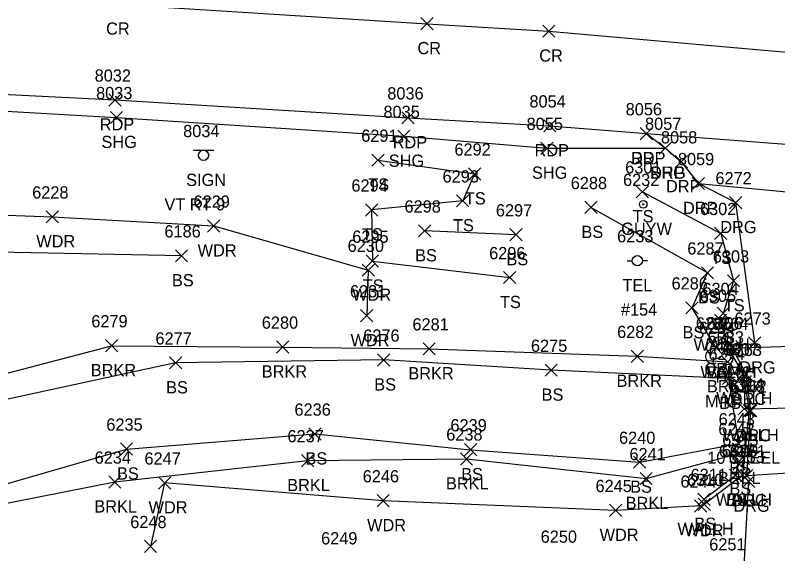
# Model space of a CAD drawing. Extents: x 1588028 to 1589597, y 137576 to 138176.
# Drawn here: x 1588574.1 to 1588699, y 137809.3 to 137897.5 of the extents above; entities that cross this region are included whole.
import ezdxf

# ---------------------------------------------------------------- set-up
doc = ezdxf.new("R2010")
doc.units = 0
for name, color, linetype in [('D_A', 7, 'Continuous'), ('D_C', 7, 'Continuous'), ('D_I', 7, 'Continuous'), ('D_TIC', 7, 'Continuous'), ('DCP', 7, 'Continuous'), ('DHW', 7, 'Continuous'), ('L_A', 7, 'Continuous'), ('L_C', 7, 'Continuous'), ('L_I', 7, 'Continuous'), ('L_TIC', 7, 'Continuous'), ('LAWA', 7, 'Continuous'), ('LAWE', 7, 'Continuous'), ('LELB', 7, 'Continuous'), ('LTD', 7, 'Continuous'), ('P_A', 7, 'Continuous'), ('P_I', 7, 'Continuous'), ('P_TIC', 7, 'Continuous'), ('PET', 7, 'Continuous'), ('PRC', 7, 'Continuous'), ('PSU', 7, 'Continuous'), ('R_A', 7, 'Continuous'), ('R_I', 7, 'Continuous'), ('R_TIC', 7, 'Continuous'), ('RDG', 7, 'Continuous'), ('RDP', 7, 'Continuous'), ('S_A', 7, 'Continuous'), ('S_C', 7, 'Continuous'), ('S_I', 7, 'Continuous'), ('SSGN', 7, 'Continuous'), ('U_A', 7, 'Continuous'), ('U_C', 7, 'Continuous'), ('U_I', 7, 'Continuous'), ('UP', 7, 'Continuous'), ('UPGW', 7, 'Continuous')]:
    doc.layers.add(name, color=color, linetype=linetype)

msp = doc.modelspace()

# ---------------------------------------------------------------- linework, layer by layer
at = {"layer": 'D_TIC'}
for points in [[(1588688.65, 137846.55), (1588690.65, 137848.55)], [(1588690.65, 137846.55), (1588688.65, 137848.55)], [(1588689.78, 137842.06), (1588691.78, 137844.06)], [(1588691.78, 137842.06), (1588689.78, 137844.06)], [(1588692.37, 137837.77), (1588694.37, 137839.77)], [(1588694.37, 137837.77), (1588692.37, 137839.77)], [(1588692.57, 137832.03), (1588694.57, 137834.03)], [(1588694.57, 137832.03), (1588692.57, 137834.03)], [(1588693.38, 137831.74), (1588695.38, 137833.74)], [(1588695.38, 137831.74), (1588693.38, 137833.74)], [(1588692.29, 137821.18), (1588694.29, 137823.18)], [(1588694.29, 137821.18), (1588692.29, 137823.18)], [(1588686, 137816.39), (1588688, 137818.39)], [(1588688, 137816.39), (1588686, 137818.39)]]:
    msp.add_lwpolyline(points, dxfattribs=at)
at = {"layer": 'DCP'}
msp.add_lwpolyline([(1588693.57, 137833.03), (1588709.71, 137833.36)], dxfattribs=at)
at = {"layer": 'DHW'}
msp.add_lwpolyline([(1588689.65, 137847.55), (1588690.78, 137843.06), (1588693.37, 137838.77), (1588694.38, 137832.74), (1588693.29, 137822.18), (1588687, 137817.39)], dxfattribs=at)
at = {"layer": 'L_TIC'}
for points in [[(1588632.53, 137872.75), (1588634.53, 137874.75)], [(1588634.53, 137872.75), (1588632.53, 137874.75)], [(1588648.36, 137870.5), (1588650.36, 137872.5)], [(1588650.36, 137870.5), (1588648.36, 137872.5)], [(1588675.86, 137867.57), (1588677.86, 137869.57)], [(1588677.86, 137867.57), (1588675.86, 137869.57)], [(1588646.42, 137866.09), (1588648.42, 137868.09)], [(1588648.42, 137866.09), (1588646.42, 137868.09)], [(1588667.43, 137865.01), (1588669.43, 137867.01)], [(1588669.43, 137865.01), (1588667.43, 137867.01)], [(1588631.49, 137864.6), (1588633.49, 137866.6)], [(1588633.49, 137864.6), (1588631.49, 137866.6)], [(1588579.18, 137863.47), (1588581.18, 137865.47)], [(1588581.18, 137863.47), (1588579.18, 137865.47)], [(1588605.62, 137861.97), (1588607.62, 137863.97)], [(1588607.62, 137861.97), (1588605.62, 137863.97)], [(1588640.18, 137861.17), (1588642.18, 137863.17)], [(1588642.18, 137861.17), (1588640.18, 137863.17)], [(1588655.15, 137860.54), (1588657.15, 137862.54)], [(1588657.15, 137860.54), (1588655.15, 137862.54)], [(1588688.69, 137860.76), (1588690.69, 137862.76)], [(1588690.69, 137860.76), (1588688.69, 137862.76)], [(1588600.33, 137857.09), (1588602.33, 137859.09)], [(1588602.33, 137857.09), (1588600.33, 137859.09)], [(1588631.62, 137856.22), (1588633.62, 137858.22)], [(1588633.62, 137856.22), (1588631.62, 137858.22)], [(1588630.95, 137854.73), (1588632.95, 137856.73)], [(1588632.95, 137854.73), (1588630.95, 137856.73)], [(1588686.52, 137854.29), (1588688.52, 137856.29)], [(1588688.52, 137854.29), (1588686.52, 137856.29)], [(1588654.12, 137853.53), (1588656.12, 137855.53)], [(1588656.12, 137853.53), (1588654.12, 137855.53)], [(1588690.79, 137852.99), (1588692.79, 137854.99)], [(1588692.79, 137852.99), (1588690.79, 137854.99)], [(1588684, 137848.57), (1588686, 137850.57)], [(1588686, 137848.57), (1588684, 137850.57)], [(1588689.09, 137847.66), (1588691.09, 137849.66)], [(1588691.09, 137847.66), (1588689.09, 137849.66)], [(1588630.68, 137847.28), (1588632.68, 137849.28)], [(1588632.68, 137847.28), (1588630.68, 137849.28)], [(1588588.88, 137842.37), (1588590.88, 137844.37)], [(1588590.88, 137842.37), (1588588.88, 137844.37)], [(1588616.9, 137842.15), (1588618.9, 137844.15)], [(1588618.9, 137842.15), (1588616.9, 137844.15)], [(1588640.92, 137841.86), (1588642.92, 137843.86)], [(1588642.92, 137841.86), (1588640.92, 137843.86)], [(1588687.93, 137842.01), (1588689.93, 137844.01)], [(1588689.93, 137842.01), (1588687.93, 137844.01)], [(1588633.48, 137840.03), (1588635.48, 137842.03)], [(1588635.48, 137840.03), (1588633.48, 137842.03)], [(1588675.03, 137840.63), (1588677.03, 137842.63)], [(1588677.03, 137840.63), (1588675.03, 137842.63)], [(1588599.38, 137839.56), (1588601.38, 137841.56)], [(1588601.38, 137839.56), (1588599.38, 137841.56)], [(1588689.85, 137839.73), (1588691.85, 137841.73)], [(1588691.85, 137839.73), (1588689.85, 137841.73)], [(1588660.91, 137838.36), (1588662.91, 137840.36)], [(1588662.91, 137838.36), (1588660.91, 137840.36)], [(1588690, 137837.01), (1588692, 137839.01)], [(1588692, 137837.01), (1588690, 137839.01)], [(1588622.21, 137827.91), (1588624.21, 137829.91)], [(1588624.21, 137827.91), (1588622.21, 137829.91)], [(1588691.66, 137826.33), (1588693.66, 137828.33)], [(1588693.66, 137826.33), (1588691.66, 137828.33)], [(1588591.33, 137825.45), (1588593.33, 137827.45)], [(1588593.33, 137825.45), (1588591.33, 137827.45)], [(1588647.72, 137825.34), (1588649.72, 137827.34)], [(1588649.72, 137825.34), (1588647.72, 137827.34)], [(1588647.03, 137823.83), (1588649.03, 137825.83)], [(1588649.03, 137823.83), (1588647.03, 137825.83)], [(1588691.6, 137824.72), (1588693.6, 137826.72)], [(1588693.6, 137824.72), (1588691.6, 137826.72)], [(1588621.01, 137823.55), (1588623.01, 137825.55)], [(1588623.01, 137823.55), (1588621.01, 137825.55)], [(1588675.42, 137823.29), (1588677.42, 137825.29)], [(1588677.42, 137823.29), (1588675.42, 137825.29)], [(1588691.68, 137822.96), (1588693.68, 137824.96)], [(1588693.68, 137822.96), (1588691.68, 137824.96)], [(1588589.41, 137820.05), (1588591.41, 137822.05)], [(1588591.41, 137820.05), (1588589.41, 137822.05)], [(1588676.48, 137820.62), (1588678.48, 137822.62)], [(1588678.48, 137820.62), (1588676.48, 137822.62)], [(1588691.13, 137821.14), (1588693.13, 137823.14)], [(1588693.13, 137821.14), (1588691.13, 137823.14)], [(1588597.57, 137819.9), (1588599.57, 137821.9)], [(1588599.57, 137819.9), (1588597.57, 137821.9)], [(1588633.39, 137816.99), (1588635.39, 137818.99)], [(1588635.39, 137816.99), (1588633.39, 137818.99)], [(1588685.94, 137817.21), (1588687.94, 137819.21)], [(1588687.94, 137817.21), (1588685.94, 137819.21)], [(1588671.48, 137815.4), (1588673.48, 137817.4)], [(1588673.48, 137815.4), (1588671.48, 137817.4)], [(1588685.41, 137816.13), (1588687.41, 137818.13)], [(1588687.41, 137816.13), (1588685.41, 137818.13)], [(1588595.25, 137809.5), (1588597.25, 137811.5)], [(1588597.25, 137809.5), (1588595.25, 137811.5)]]:
    msp.add_lwpolyline(points, dxfattribs=at)
at = {"layer": 'LAWA'}
for points in [[(1588398.21, 137876.79), (1588441.82, 137872.12), (1588481.62, 137869.65), (1588505.62, 137869.07), (1588523.45, 137867.77), (1588551.7, 137865.51), (1588580.18, 137864.47), (1588606.62, 137862.97), (1588631.95, 137855.73), (1588631.68, 137848.28)], [(1588686.41, 137817.13), (1588672.48, 137816.4), (1588634.39, 137817.99), (1588598.57, 137820.9), (1588596.25, 137810.5)]]:
    msp.add_lwpolyline(points, dxfattribs=at)
at = {"layer": 'LAWE'}
for points in [[(1588351.94, 137757.61), (1588394.8, 137793.11), (1588433.62, 137803.03), (1588480.63, 137811.17), (1588520.35, 137821.08), (1588567.54, 137837.49), (1588589.88, 137843.37), (1588617.9, 137843.15), (1588641.92, 137842.86), (1588676.03, 137841.63), (1588690.85, 137840.73)], [(1588391.31, 137757.57), (1588423.17, 137774.38), (1588459.5, 137784.96), (1588499.39, 137790.91), (1588529.2, 137803.77), (1588565.73, 137816.22), (1588590.41, 137821.05), (1588622.01, 137824.55), (1588648.03, 137824.83), (1588677.48, 137821.62), (1588692.6, 137825.72)]]:
    msp.add_lwpolyline(points, dxfattribs=at)
at = {"layer": 'LELB'}
for points in [[(1588633.53, 137873.75), (1588649.36, 137871.5), (1588647.42, 137867.09), (1588632.49, 137865.6), (1588632.62, 137857.22), (1588655.12, 137854.53)], [(1588676.86, 137868.57), (1588689.69, 137861.76), (1588691.79, 137853.99), (1588690.09, 137848.66)], [(1588688.93, 137843.01), (1588685, 137849.57), (1588687.52, 137855.29), (1588668.43, 137866.01)], [(1588656.15, 137861.54), (1588641.18, 137862.17)], [(1588601.33, 137858.09), (1588565.74, 137858.78), (1588552.32, 137849.2), (1588523.84, 137845.09), (1588499.09, 137858.03), (1588496.21, 137836.26), (1588469.92, 137835.97)], [(1588391.4, 137759.65), (1588422.67, 137775.93), (1588458.34, 137787.99), (1588495.41, 137796.88), (1588527.54, 137805.18), (1588563.3, 137818.09), (1588592.33, 137826.45), (1588623.21, 137828.91), (1588648.72, 137826.34), (1588676.42, 137824.29), (1588692.66, 137827.33), (1588691, 137838.01), (1588661.91, 137839.36), (1588634.48, 137841.03), (1588600.38, 137840.56), (1588568.3, 137833.61)], [(1588686.94, 137818.21), (1588692.13, 137822.14), (1588692.68, 137823.96)]]:
    msp.add_lwpolyline(points, dxfattribs=at)
at = {"layer": 'LTD'}
msp.add_line((1588689.43, 137842.3), (1588689.43, 137842.3), dxfattribs=at)
msp.add_line((1588689.43, 137842.3), (1588689.43, 137842.3), dxfattribs=at)
msp.add_arc((1588689.48, 137843.74), 1.05, 335.5272, 180.9563, dxfattribs=at)
for centre, major_axis, ratio, start_param, end_param in [((1588688.64, 137842.97), (1.21, -0.51), 0.895232, 1.570796, 4.712389), ((1588689.22, 137842.76), (-0.208, -0.792), 0.645439, 3.141593, 6.283185), ((1588690.47, 137842.89), (-1.14, -0.48), 0.949671, 1.570796, 4.712389), ((1588688.35, 137841.59), (0.58, -1.04), 0.959034, 3.141593, 6.283185), ((1588689.93, 137842.14), (-0.5, 0.667), 0.989748, 3.141593, 6.283185), ((1588690.43, 137841.47), (-1.09, 0.79), 0.841452, 1.570796, 4.712389), ((1588689.43, 137840.8), (0.26, 1.06), 0.942809, 1.570796, 4.712389), ((1588688.97, 137841.55), (-0.625, -0.083), 0.423636, 0, 3.141593)]:
    msp.add_ellipse(centre, major_axis=major_axis, ratio=ratio, start_param=start_param, end_param=end_param, dxfattribs=at)
at = {"layer": 'P_TIC'}
for points in [[(1588640.57, 137895.1), (1588642.57, 137897.1)], [(1588642.57, 137895.1), (1588640.57, 137897.1)], [(1588660.53, 137893.88), (1588662.53, 137895.88)], [(1588662.53, 137893.88), (1588660.53, 137895.88)], [(1588589.45, 137882.61), (1588591.45, 137884.61)], [(1588591.45, 137882.61), (1588589.45, 137884.61)], [(1588589.68, 137879.74), (1588591.68, 137881.74)], [(1588591.68, 137879.74), (1588589.68, 137881.74)], [(1588637.45, 137879.69), (1588639.45, 137881.69)], [(1588639.45, 137879.69), (1588637.45, 137881.69)], [(1588660.69, 137878.38), (1588662.69, 137880.38)], [(1588662.69, 137878.38), (1588660.69, 137880.38)], [(1588636.76, 137876.66), (1588638.76, 137878.66)], [(1588638.76, 137876.66), (1588636.76, 137878.66)], [(1588676.51, 137877.09), (1588678.51, 137879.09)], [(1588678.51, 137877.09), (1588676.51, 137879.09)], [(1588660.23, 137874.7), (1588662.23, 137876.7)], [(1588662.23, 137874.7), (1588660.23, 137876.7)], [(1588679.63, 137874.71), (1588681.63, 137876.71)], [(1588681.63, 137874.71), (1588679.63, 137876.71)]]:
    msp.add_lwpolyline(points, dxfattribs=at)
at = {"layer": 'PET'}
msp.add_lwpolyline([(1588419.97, 137892.51), (1588466.09, 137889.91), (1588506.76, 137888.01), (1588548, 137885.78), (1588590.45, 137883.61), (1588638.45, 137880.69), (1588661.69, 137879.38), (1588677.51, 137878.09), (1588721.13, 137874.78), (1588740.19, 137872.99), (1588782.63, 137867.93), (1588820.21, 137862.87), (1588860.26, 137857.26), (1588914.01, 137849.9), (1588927.99, 137847.51)], dxfattribs=at)
at = {"layer": 'PRC'}
msp.add_lwpolyline([(1588420.99, 137907.2), (1588467.18, 137904.92), (1588507.29, 137903.21), (1588549.37, 137901.19), (1588590.55, 137899.3), (1588641.57, 137896.1), (1588661.53, 137894.88), (1588702.39, 137891.26), (1588744.44, 137887.15), (1588784.4, 137882.3), (1588823.71, 137877.3), (1588862.06, 137871.74), (1588917.24, 137863.85)], dxfattribs=at)
at = {"layer": 'PSU'}
msp.add_lwpolyline([(1588419.69, 137889.11), (1588465.62, 137886.91), (1588506.57, 137885.14), (1588547.79, 137883.19), (1588590.68, 137880.74), (1588637.76, 137877.66), (1588661.23, 137875.7), (1588680.63, 137875.71)], dxfattribs=at)
at = {"layer": 'R_TIC'}
for points in [[(1588676.51, 137877.09), (1588678.51, 137879.09)], [(1588678.51, 137877.09), (1588676.51, 137879.09)], [(1588679.63, 137874.71), (1588681.63, 137876.71)], [(1588681.63, 137874.71), (1588679.63, 137876.71)], [(1588682.24, 137872.49), (1588684.24, 137874.49)], [(1588684.24, 137872.49), (1588682.24, 137874.49)], [(1588685.03, 137868.93), (1588687.03, 137870.93)], [(1588687.03, 137868.93), (1588685.03, 137870.93)], [(1588691.14, 137865.8), (1588693.14, 137867.8)], [(1588693.14, 137865.8), (1588691.14, 137867.8)], [(1588694.25, 137842.82), (1588696.25, 137844.82)], [(1588696.25, 137842.82), (1588694.25, 137844.82)], [(1588690.61, 137841.95), (1588692.61, 137843.95)], [(1588692.61, 137841.95), (1588690.61, 137843.95)], [(1588692.86, 137837.68), (1588694.86, 137839.68)], [(1588694.86, 137837.68), (1588692.86, 137839.68)], [(1588693.64, 137831.7), (1588695.64, 137833.7)], [(1588695.64, 137831.7), (1588693.64, 137833.7)], [(1588692.95, 137821.08), (1588694.95, 137823.08)], [(1588694.95, 137821.08), (1588692.95, 137823.08)], [(1588693.29, 137820.17), (1588695.29, 137822.17)], [(1588695.29, 137820.17), (1588693.29, 137822.17)]]:
    msp.add_lwpolyline(points, dxfattribs=at)
at = {"layer": 'RDG'}
for points in [[(1588692.14, 137866.8), (1588686.03, 137869.93)], [(1588692.14, 137866.8), (1588695.25, 137843.82)], [(1588693.3, 137803.33), (1588694.29, 137821.17)]]:
    msp.add_lwpolyline(points, dxfattribs=at)
at = {"layer": 'RDP'}
for points in [[(1588677.51, 137878.09), (1588680.63, 137875.71), (1588683.24, 137873.49), (1588686.03, 137869.93), (1588712.1, 137867.48), (1588714.28, 137870.34), (1588718.55, 137872.99), (1588721.13, 137874.78)], [(1588693.95, 137822.08), (1588694.64, 137832.7), (1588693.86, 137838.68), (1588691.61, 137842.95), (1588709.04, 137843.58), (1588708.54, 137832.84), (1588710.89, 137823.14)], [(1588710.89, 137823.14), (1588693.95, 137822.08)]]:
    msp.add_lwpolyline(points, dxfattribs=at)
at = {"layer": 'SSGN'}
for p, q in [((1588603.32, 137875.38), (1588606.65, 137875.38)), ((1588604.96, 137874.54), (1588604.96, 137874.54))]:
    msp.add_line(p, q, dxfattribs=at)
msp.add_circle((1588604.96, 137874.54), 0.833, dxfattribs=at)
at = {"layer": 'UP'}
for p, q in [((1588674.37, 137857.29), (1588675.2, 137857.29)), ((1588676.03, 137857.29), (1588676.03, 137857.29)), ((1588677.7, 137857.29), (1588676.86, 137857.29)), ((1588676.86, 137857.29), (1588676.86, 137857.29)), ((1588677.7, 137857.29), (1588677.7, 137857.29))]:
    msp.add_line(p, q, dxfattribs=at)
msp.add_circle((1588676.03, 137857.29), 0.833, dxfattribs=at)
at = {"layer": 'UPGW'}
for radius in [0.625, 0.0833]:
    msp.add_circle((1588676.99, 137866.52), radius, dxfattribs=at)

# ---------------------------------------------------------------- texts
at = {"layer": 'D_A'}
for s, p in [('WALLH', (1588685.24, 137842.55)), ('WALLH', (1588686.37, 137838.06)), ('WALLH', (1588688.96, 137833.77)), ('WALLH', (1588689.98, 137827.74)), ('P', (1588692.94, 137828.03)), ('WALLH', (1588688.88, 137817.18)), ('WALLH', (1588682.6, 137812.39))]:
    msp.add_text(s, height=2, dxfattribs=at).set_placement(p)
at = {"layer": 'D_C'}
for s, p in [('CRM', (1588687.02, 137838.55)), ("10'STEEL", (1588687.49, 137824.03))]:
    msp.add_text(s, height=2, dxfattribs=at).set_placement(p)
at = {"layer": 'D_I'}
for s, p in [('6305', (1588686.26, 137850.55)), ('6306', (1588687.34, 137846.06)), ('6307', (1588689.99, 137841.77)), ('6314', (1588690.83, 137836.03)), ('6308', (1588691, 137835.74)), ('6309', (1588689.9, 137825.18)), ('6310', (1588684.18, 137820.39))]:
    msp.add_text(s, height=2, dxfattribs=at).set_placement(p)
at = {"layer": 'L_A'}
for s, p in [('TS', (1588631.94, 137868.75)), ('TS', (1588647.77, 137866.5)), ('TS', (1588675.27, 137863.57)), ('TS', (1588645.83, 137862.09)), ('TS', (1588630.9, 137860.6)), ('BS', (1588666.87, 137861.01)), ('WDR', (1588577.54, 137859.47)), ('WDR', (1588603.98, 137857.97)), ('BS', (1588639.62, 137857.17)), ('BS', (1588654.59, 137856.54)), ('TS', (1588688.1, 137856.76)), ('BS', (1588599.77, 137853.09)), ('TS', (1588631.03, 137852.22)), ('WDR', (1588629.31, 137850.73)), ('BS', (1588685.97, 137850.29)), ('TS', (1588653.52, 137849.53)), ('TS', (1588690.2, 137848.99)), ('BS', (1588683.44, 137844.57)), ('WDR', (1588629.04, 137843.28)), ('TS', (1588688.5, 137843.66)), ('BRKR', (1588586.47, 137838.37)), ('BRKR', (1588614.49, 137838.15)), ('BRKR', (1588638.51, 137837.86)), ('BS', (1588687.37, 137838.01)), ('BRKR', (1588672.62, 137836.63)), ('H', (1588688.86, 137837.3)), ('BS', (1588598.82, 137835.56)), ('BS', (1588632.92, 137836.03)), ('BRKR', (1588687.44, 137835.73)), ('BS', (1588660.35, 137834.36)), ('BS', (1588689.44, 137833.01)), ('BS', (1588621.65, 137823.91)), ('BS', (1588590.77, 137821.45)), ('BS', (1588647.17, 137821.34)), ('BS', (1588691.1, 137822.33)), ('BRKL', (1588689.25, 137820.72)), ('BRKL', (1588618.66, 137819.55)), ('BRKL', (1588644.67, 137819.83)), ('BS', (1588674.86, 137819.29)), ('BS', (1588691.13, 137818.96)), ('BRKL', (1588674.12, 137816.62)), ('BS', (1588690.57, 137817.14)), ('BRKL', (1588587.06, 137816.05)), ('WDR', (1588595.94, 137815.9)), ('WDR', (1588631.75, 137812.99)), ('BS', (1588685.38, 137813.21)), ('WDR', (1588669.85, 137811.4)), ('WDR', (1588683.77, 137812.13))]:
    msp.add_text(s, height=2, dxfattribs=at).set_placement(p)
at = {"layer": 'L_C'}
msp.add_text('M.M', height=2, dxfattribs=at).set_placement((1588687.13, 137833.3))
at = {"layer": 'L_I'}
for s, p in [('6291', (1588630.79, 137876.75)), ('6292', (1588646.06, 137874.5)), ('6301', (1588674.04, 137871.57)), ('6293', (1588644.11, 137870.09)), ('6288', (1588665.12, 137869.01)), ('6228', (1588576.87, 137867.47)), ('6294', (1588629.18, 137868.6)), ('6229', (1588603.31, 137865.97)), ('6298', (1588637.88, 137865.17)), ('6297', (1588652.85, 137864.54)), ('6302', (1588686.3, 137864.76)), ('6186', (1588598.54, 137861.09)), ('6295', (1588629.32, 137860.22)), ('6230', (1588628.56, 137858.73)), ('6296', (1588651.75, 137857.53)), ('6287', (1588684.22, 137858.29)), ('6303', (1588688.4, 137856.99)), ('6286', (1588681.64, 137852.57)), ('6231', (1588628.94, 137851.28)), ('6304', (1588686.7, 137851.66)), ('6279', (1588586.56, 137846.37)), ('6280', (1588614.5, 137846.15)), ('6281', (1588639.18, 137845.86)), ('6285', (1588685.62, 137846.01)), ('6284', (1588686.12, 137845.3)), ('6276', (1588631.12, 137844.03)), ('6282', (1588672.72, 137844.63)), ('6283', (1588687.55, 137843.73)), ('6277', (1588597.07, 137843.56)), ('6275', (1588658.6, 137842.36)), ('6274', (1588687.69, 137841.01)), ('6236', (1588619.85, 137831.91)), ('6243', (1588689.35, 137830.33)), ('6235', (1588589.02, 137829.45)), ('6239', (1588645.41, 137829.34)), ('6242', (1588689.3, 137828.72)), ('6237', (1588618.7, 137827.55)), ('6238', (1588644.72, 137827.83)), ('6240', (1588673.03, 137827.29)), ('6313', (1588689.94, 137826.96)), ('6312', (1588689.39, 137825.14)), ('6234', (1588587.1, 137824.05)), ('6247', (1588595.27, 137823.9)), ('6241', (1588674.74, 137824.62)), ('6311', (1588684.76, 137821.21)), ('6246', (1588631.03, 137820.99)), ('6244', (1588683.1, 137820.13)), ('6245', (1588669.18, 137819.4)), ('6248', (1588592.94, 137813.5)), ('6249', (1588624.21, 137810.83)), ('6250', (1588660.19, 137811.1)), ('6251', (1588687.81, 137809.84))]:
    msp.add_text(s, height=2, dxfattribs=at).set_placement(p)
at = {"layer": 'P_A'}
for s, p in [('CR', (1588588.98, 137894.3)), ('CR', (1588640, 137891.1)), ('CR', (1588659.96, 137889.88)), ('RDP', (1588587.94, 137878.61)), ('SHG', (1588588.22, 137875.74)), ('RDP', (1588635.94, 137875.69)), ('RDP', (1588659.18, 137874.38)), ('SHG', (1588635.3, 137872.66)), ('RDP', (1588675, 137873.09)), ('SHG', (1588658.77, 137870.7)), ('SHG', (1588678.17, 137870.71))]:
    msp.add_text(s, height=2, dxfattribs=at).set_placement(p)
at = {"layer": 'P_I'}
for s, p in [('8032', (1588587.11, 137886.61)), ('8033', (1588587.34, 137883.74)), ('8036', (1588635.06, 137883.69)), ('8054', (1588658.35, 137882.38)), ('8035', (1588634.43, 137880.66)), ('8056', (1588674.12, 137881.09)), ('8055', (1588657.89, 137878.7)), ('8057', (1588677.29, 137878.71))]:
    msp.add_text(s, height=2, dxfattribs=at).set_placement(p)
at = {"layer": 'R_A'}
for s, p in [('DRP', (1588675, 137873.09)), ('DRP', (1588678.12, 137870.71)), ('DRP', (1588680.73, 137868.49)), ('DRP', (1588683.51, 137864.93)), ('DRG', (1588689.62, 137861.8)), ('DRG', (1588692.74, 137838.82)), ('DRC', (1588689.1, 137837.95)), ('DRC', (1588691.35, 137833.68)), ('DRC', (1588692.13, 137827.7)), ('DRC', (1588691.44, 137817.08)), ('DRG', (1588691.78, 137816.17))]:
    msp.add_text(s, height=2, dxfattribs=at).set_placement(p)
at = {"layer": 'R_I'}
for s, p in [('8056', (1588674.12, 137881.09)), ('8057', (1588677.29, 137878.71)), ('8058', (1588679.9, 137876.49)), ('8059', (1588682.68, 137872.93)), ('6272', (1588688.83, 137869.8)), ('6273', (1588691.95, 137846.82)), ('6264', (1588688.26, 137845.95)), ('6263', (1588690.51, 137841.68)), ('6262', (1588691.29, 137835.7)), ('6261', (1588691.16, 137825.08)), ('6253', (1588690.98, 137824.17))]:
    msp.add_text(s, height=2, dxfattribs=at).set_placement(p)
at = {"layer": 'S_A'}
msp.add_text('SIGN', height=2, dxfattribs=at).set_placement((1588602.1, 137869.52))
at = {"layer": 'S_C'}
msp.add_text('VT RT 9', height=2, dxfattribs=at).set_placement((1588598.54, 137865.52))
at = {"layer": 'S_I'}
msp.add_text('8034', height=2, dxfattribs=at).set_placement((1588601.61, 137877.52))
at = {"layer": 'U_A'}
for s, p in [('GUYW', (1588673.39, 137861.52)), ('TEL', (1588673.59, 137852.29))]:
    msp.add_text(s, height=2, dxfattribs=at).set_placement(p)
at = {"layer": 'U_C'}
msp.add_text('#154', height=2, dxfattribs=at).set_placement((1588673.34, 137848.29))
at = {"layer": 'U_I'}
for s, p in [('6232', (1588673.69, 137869.52)), ('6233', (1588672.72, 137860.29))]:
    msp.add_text(s, height=2, dxfattribs=at).set_placement(p)

doc.saveas('drawing.dxf')
